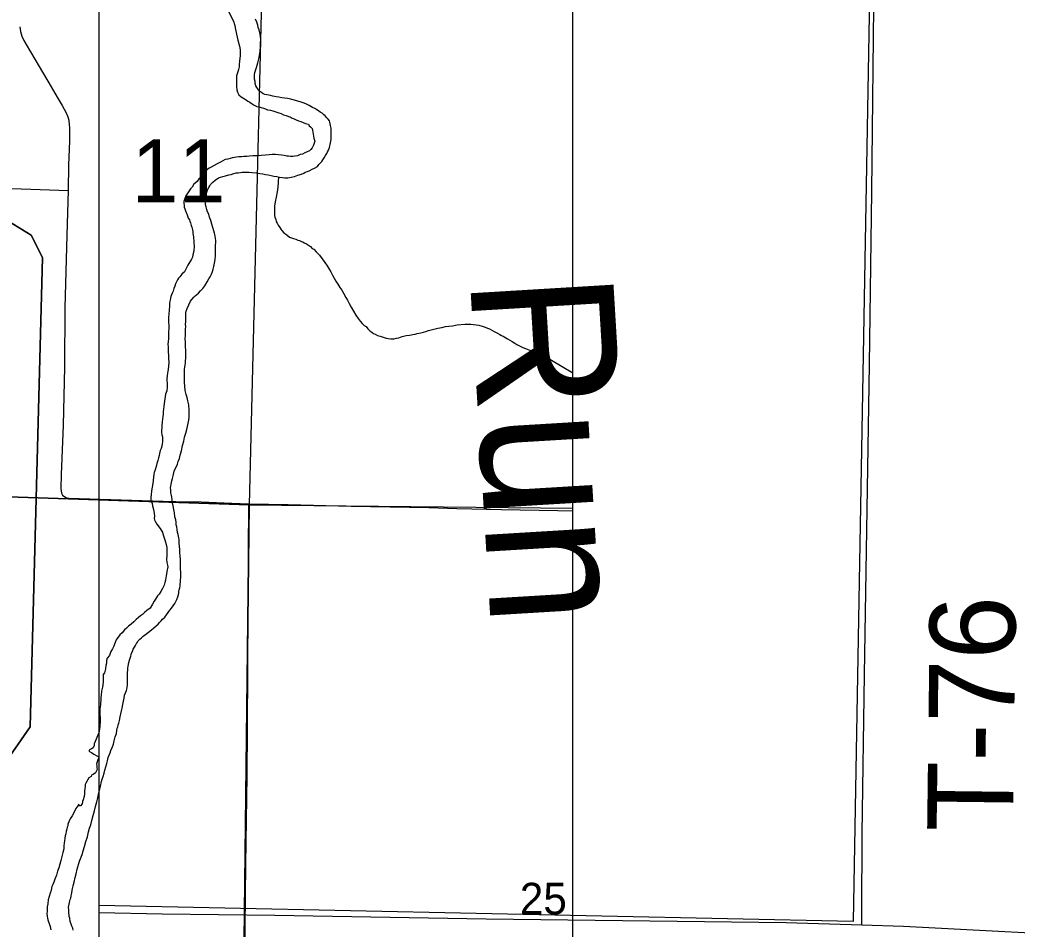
# Model space of a CAD drawing. Extents: x 0 to 68, y 0 to 52.9.
# Drawn here: x 49.378 to 51.122, y 39.684 to 41.274 of the extents above; entities that cross this region are included whole.
import ezdxf

# ---------------------------------------------------------------- set-up
doc = ezdxf.new("R2010")
doc.units = 0
for name, color, linetype in [('Default', 7, 'Continuous'), ('GM_X_County_Road', 7, 'Continuous'), ('GM_X_Minor_Lake', 7, 'Continuous'), ('GM_X_Minor_River', 7, 'Continuous'), ('GM_X_Minor_River_Text', 7, 'Continuous'), ('GM_X_Township_Road', 7, 'Continuous'), ('GM_X_Township_Road_Text', 7, 'Continuous')]:
    doc.layers.add(name, color=color, linetype=linetype)

msp = doc.modelspace()

# ---------------------------------------------------------------- linework, layer by layer
at = {"layer": 'Default'}
for p, q in [((49.5172, 34.4614), (49.5172, 52.9414)), ((50.3451, 32.7683), (50.3451, 42.0083))]:
    msp.add_line(p, q, dxfattribs=at)
for points in [[(49.5172, 42.3674), (50.8824, 42.3391), (50.8358, 39.6972), (49.5172, 39.725)], [(49.7428, 41.2905), (49.7526, 41.2698), (49.7531, 41.2673), (49.754, 41.2637), (49.755, 41.2597), (49.7574, 41.2486), (49.7597, 41.2381), (49.7621, 41.228), (49.7636, 41.2214), (49.7635, 41.2169), (49.7635, 41.2129), (49.7634, 41.2104), (49.7629, 41.2074), (49.7623, 41.2009), (49.7617, 41.1963), (49.7617, 41.1918), (49.7606, 41.1873), (49.7595, 41.1828), (49.7585, 41.1793), (49.7574, 41.1758), (49.7569, 41.1708), (49.7572, 41.1572), (49.7576, 41.1517), (49.7586, 41.1477), (49.7611, 41.1426), (49.7655, 41.1395), (49.771, 41.136), (49.774, 41.1339), (49.777, 41.1319), (49.7805, 41.1298), (49.7845, 41.1272), (49.788, 41.1247), (49.7925, 41.1226), (49.7965, 41.1216), (49.8001, 41.1205), (49.8041, 41.1194), (49.8081, 41.1184), (49.8116, 41.1168), (49.8166, 41.1158), (49.8206, 41.1147), (49.8241, 41.1137), (49.8277, 41.1126), (49.8312, 41.1111), (49.8352, 41.11), (49.8392, 41.1079), (49.8442, 41.1064), (49.8482, 41.1048), (49.8512, 41.1043), (49.8547, 41.1022), (49.8577, 41.1007), (49.8617, 41.0991), (49.8657, 41.0975), (49.8697, 41.096), (49.8738, 41.0944), (49.8778, 41.0929), (49.8803, 41.0923), (49.8828, 41.0913)], [(49.8893, 41.0129), (49.8934, 41.0148), (49.8985, 41.0173), (49.901, 41.0207), (49.9036, 41.0232), (49.9061, 41.0262), (49.9082, 41.0292), (49.9107, 41.0327), (49.9128, 41.0367), (49.9149, 41.0401), (49.9164, 41.0431), (49.918, 41.0461), (49.9195, 41.0506), (49.9216, 41.0586), (49.9222, 41.0616), (49.9227, 41.0646), (49.9228, 41.0687), (49.9228, 41.0727), (49.9229, 41.0762), (49.9229, 41.0792), (49.9224, 41.0817), (49.9225, 41.0842), (49.9215, 41.0893), (49.9211, 41.0918), (49.9201, 41.0948), (49.9196, 41.0973), (49.9176, 41.1004), (49.9151, 41.1024), (49.9122, 41.106), (49.9097, 41.108), (49.9067, 41.1106), (49.9037, 41.1126), (49.9007, 41.1147), (49.8977, 41.1167), (49.8942, 41.1188), (49.8902, 41.1208), (49.8842, 41.1239), (49.8797, 41.1265), (49.8752, 41.1281), (49.8702, 41.1301), (49.8642, 41.1317), (49.8581, 41.1333), (49.8521, 41.1349), (49.8466, 41.1365), (49.8416, 41.137), (49.8365, 41.1376), (49.831, 41.1387), (49.8265, 41.1392), (49.8204, 41.1403), (49.8164, 41.1414), (49.8134, 41.1419), (49.8099, 41.1425), (49.8064, 41.1435), (49.8039, 41.1446), (49.8009, 41.1466), (49.7974, 41.1492), (49.7949, 41.1517), (49.7924, 41.1558), (49.791, 41.1583), (49.79, 41.1623), (49.7895, 41.1658), (49.7886, 41.1704), (49.7886, 41.1744), (49.7887, 41.1779), (49.7892, 41.1819), (49.7903, 41.1854), (49.7919, 41.1904), (49.7934, 41.1944), (49.7945, 41.1989), (49.7956, 41.2034), (49.7966, 41.2079), (49.7972, 41.2125), (49.7977, 41.215), (49.7983, 41.2195), (49.7989, 41.226), (49.799, 41.2335), (49.7995, 41.2395), (49.7991, 41.2441), (49.7987, 41.2486), (49.7977, 41.2511), (49.7967, 41.2562), (49.7953, 41.2607), (49.7943, 41.2647), (49.7924, 41.2698), (49.7904, 41.2753)], [(49.8828, 41.0913), (49.8843, 41.0888), (49.8867, 41.0867), (49.8897, 41.0837), (49.8902, 41.0811), (49.8911, 41.0741), (49.8925, 41.0671), (49.894, 41.0615), (49.8919, 41.055), (49.8893, 41.05), (49.8873, 41.047), (49.8847, 41.0451), (49.8807, 41.0431), (49.8766, 41.0411), (49.8726, 41.0392), (49.8685, 41.0382), (49.864, 41.0363), (49.8594, 41.0353), (49.8554, 41.0349), (49.8518, 41.0349), (49.8483, 41.0355), (49.8453, 41.0355), (49.8403, 41.0366), (49.8358, 41.0372), (49.8307, 41.0377), (49.8252, 41.0383), (49.8197, 41.0384), (49.8141, 41.0379), (49.8081, 41.0375), (49.8005, 41.0366), (49.7924, 41.0362), (49.7859, 41.0358), (49.7798, 41.0354), (49.7753, 41.0349), (49.7698, 41.035), (49.7657, 41.0346), (49.7612, 41.0341), (49.7572, 41.0337), (49.7536, 41.0332), (49.7501, 41.0323), (49.7461, 41.0313), (49.742, 41.0304), (49.7375, 41.0294), (49.7334, 41.0275), (49.7294, 41.025), (49.7233, 41.0221), (49.7126, 41.0162), (49.7096, 41.0147), (49.704, 41.0103), (49.7009, 41.0073), (49.6984, 41.0043), (49.6953, 40.9998), (49.6912, 40.9959), (49.6886, 40.9914), (49.6851, 40.9884), (49.6825, 40.9864), (49.6795, 40.9815), (49.6769, 40.9785), (49.6743, 40.975), (49.6718, 40.9715), (49.6697, 40.968), (49.6682, 40.9655), (49.6671, 40.963), (49.6661, 40.96), (49.665, 40.9565), (49.665, 40.9525), (49.6655, 40.95), (49.6659, 40.9465), (49.6669, 40.9435), (49.6679, 40.9399), (49.6693, 40.9369), (49.6703, 40.9344), (49.6713, 40.9313), (49.6727, 40.9273), (49.6747, 40.9243), (49.6757, 40.9217), (49.6767, 40.9192), (49.6781, 40.9142), (49.6791, 40.9111), (49.68, 40.9066), (49.6805, 40.9036), (49.6809, 40.9001), (49.6819, 40.8945), (49.6828, 40.885), (49.6832, 40.8769), (49.6826, 40.8709), (49.682, 40.8669), (49.681, 40.8629), (49.6799, 40.8589), (49.6784, 40.8554), (49.6722, 40.8449), (49.6696, 40.8405), (49.666, 40.8335), (49.6614, 40.829), (49.6583, 40.8245), (49.6558, 40.8221), (49.6537, 40.8191), (49.6522, 40.8156), (49.6506, 40.8121), (49.6491, 40.8081), (49.6475, 40.8041)], [(49.6686, 40.6823), (49.6687, 40.6883), (49.6683, 40.6953), (49.6679, 40.7034), (49.668, 40.7104), (49.6675, 40.7164), (49.6681, 40.7214), (49.6677, 40.7275), (49.6678, 40.733), (49.6683, 40.7375), (49.6679, 40.742), (49.6684, 40.746), (49.6685, 40.7506), (49.6685, 40.7546), (49.6686, 40.7581), (49.6686, 40.7616), (49.6692, 40.7646), (49.6707, 40.7691), (49.6769, 40.7821), (49.679, 40.7846), (49.6826, 40.7891), (49.6851, 40.791), (49.6877, 40.7935), (49.6907, 40.796), (49.6943, 40.7999), (49.6984, 40.8044), (49.702, 40.8089), (49.7061, 40.8159), (49.7086, 40.8209), (49.7112, 40.8248), (49.7133, 40.8293), (49.7149, 40.8338), (49.7164, 40.8378), (49.7175, 40.8423), (49.7186, 40.8483), (49.7197, 40.8549), (49.7202, 40.8619), (49.7203, 40.8699), (49.7205, 40.8785), (49.721, 40.8855), (49.7211, 40.888), (49.7206, 40.8915), (49.7197, 40.896), (49.7187, 40.9006), (49.7173, 40.9051), (49.7158, 40.9107), (49.7139, 40.9167), (49.7125, 40.9228), (49.71, 40.9288), (49.7086, 40.9339), (49.7066, 40.9379), (49.7051, 40.9424), (49.7042, 40.947), (49.7032, 40.951), (49.7028, 40.955), (49.7029, 40.9606), (49.7034, 40.9651), (49.704, 40.9686), (49.705, 40.9726), (49.7066, 40.9766), (49.7087, 40.9806), (49.7107, 40.9836), (49.7117, 40.9861), (49.7158, 40.99), (49.7199, 40.9935), (49.7255, 40.9974), (49.729, 40.9989), (49.7331, 40.9998), (49.7381, 41.0013), (49.7437, 41.0027), (49.7477, 41.0037), (49.7523, 41.0051), (49.7563, 41.0061), (49.7603, 41.0065), (49.7644, 41.007), (49.7669, 41.0074), (49.7699, 41.0074), (49.774, 41.0078), (49.7785, 41.0078), (49.7845, 41.0072), (49.7921, 41.0066), (49.7981, 41.005), (49.8031, 41.0044), (49.8076, 41.0034), (49.8127, 41.0028), (49.8177, 41.0017), (49.8227, 41.0007), (49.8277, 41.0001), (49.8323, 40.999), (49.8373, 40.998), (49.8418, 40.9979), (49.8468, 40.9978), (49.8529, 40.9988), (49.8585, 41.0002), (49.8645, 41.0021), (49.8706, 41.0041), (49.8746, 41.0055), (49.8772, 41.0075), (49.8812, 41.0089), (49.8853, 41.0104), (49.8893, 41.0129)], [(49.6475, 40.8041), (49.6464, 40.7996), (49.6449, 40.7961), (49.6433, 40.7931), (49.6423, 40.7901), (49.6417, 40.7871), (49.6412, 40.7836), (49.6401, 40.7791), (49.6401, 40.773), (49.6395, 40.766), (49.6389, 40.7595), (49.6383, 40.7535), (49.6382, 40.7485), (49.6382, 40.7454), (49.6386, 40.7394), (49.6386, 40.7344), (49.6385, 40.7284), (49.6384, 40.7228), (49.6383, 40.7168), (49.6378, 40.7108), (49.6372, 40.7068), (49.6377, 40.7023), (49.6376, 40.6977), (49.6375, 40.6927), (49.638, 40.6877), (49.6384, 40.6822), (49.6388, 40.6746), (49.6382, 40.6681), (49.6377, 40.6631), (49.6371, 40.6591), (49.6366, 40.6566), (49.636, 40.651), (49.6354, 40.647), (49.6354, 40.6435), (49.6358, 40.6385), (49.6358, 40.632), (49.6352, 40.6249), (49.6331, 40.6194), (49.6304, 40.6029), (49.6298, 40.5979), (49.6292, 40.5934), (49.6287, 40.5889), (49.6286, 40.5843), (49.6281, 40.5803), (49.6275, 40.5758), (49.6269, 40.5708), (49.6263, 40.5643), (49.6263, 40.5603), (49.6262, 40.5562), (49.6262, 40.5527), (49.6266, 40.5482), (49.6276, 40.5447), (49.6276, 40.5412), (49.6275, 40.5361), (49.627, 40.5326), (49.6264, 40.5286), (49.6253, 40.5246), (49.6238, 40.5206), (49.6227, 40.5156), (49.6217, 40.5121), (49.6206, 40.5081), (49.6195, 40.5031), (49.618, 40.4981), (49.6164, 40.4926), (49.6148, 40.4871), (49.6132, 40.4826), (49.6127, 40.4791), (49.6121, 40.4746), (49.6115, 40.4685), (49.611, 40.463), (49.6094, 40.457), (49.6083, 40.4505), (49.6077, 40.4435), (49.6071, 40.439), (49.6076, 40.4359), (49.6081, 40.4324), (49.6095, 40.4284), (49.6105, 40.4239), (49.6119, 40.4178), (49.6133, 40.4113), (49.6138, 40.4062), (49.6132, 40.4022), (49.6137, 40.3997), (49.6157, 40.3962), (49.6181, 40.3921), (49.6236, 40.3845), (49.6256, 40.3815), (49.6275, 40.3779), (49.6285, 40.3754), (49.6295, 40.3719), (49.6309, 40.3683), (49.6319, 40.3648), (49.6328, 40.3608), (49.6343, 40.3562), (49.6352, 40.3512), (49.6352, 40.3462), (49.6351, 40.3417), (49.6351, 40.3371), (49.635, 40.3306), (49.6354, 40.3251), (49.6364, 40.3206)], [(49.594, 40.1961), (49.5981, 40.199), (49.6032, 40.203), (49.6083, 40.2074), (49.6128, 40.2109), (49.6169, 40.2143), (49.62, 40.2173), (49.6225, 40.2203), (49.6256, 40.2233), (49.6276, 40.2262), (49.6317, 40.2292), (49.6348, 40.2337), (49.6378, 40.2377), (49.6404, 40.2416), (49.6435, 40.2451), (49.6465, 40.2491), (49.6491, 40.2531), (49.6512, 40.2571), (49.6527, 40.2606), (49.6548, 40.2651), (49.6564, 40.2716), (49.6564, 40.2746), (49.657, 40.2771), (49.658, 40.2806), (49.6586, 40.2841), (49.6586, 40.2876), (49.6592, 40.2906), (49.6592, 40.2946), (49.6598, 40.2987), (49.6598, 40.3027), (49.6598, 40.3057), (49.6599, 40.3087), (49.6594, 40.3127), (49.659, 40.3172), (49.6591, 40.3233), (49.6592, 40.3303), (49.6587, 40.3368), (49.6583, 40.3424), (49.6579, 40.3479), (49.6574, 40.3529), (49.657, 40.3595), (49.6566, 40.3645), (49.6561, 40.368), (49.6556, 40.371), (49.6552, 40.3741), (49.6542, 40.3776), (49.6533, 40.3826), (49.6528, 40.3871), (49.6519, 40.3907), (49.6514, 40.3957), (49.651, 40.3997), (49.6495, 40.4048), (49.6486, 40.4118), (49.6477, 40.4178), (49.6462, 40.4239), (49.6453, 40.4294), (49.6444, 40.436), (49.6434, 40.442), (49.6425, 40.447), (49.6421, 40.4521), (49.6416, 40.4556), (49.6421, 40.4586), (49.6427, 40.4621), (49.6443, 40.4676), (49.6453, 40.4721), (49.6464, 40.4766), (49.6475, 40.4816), (49.648, 40.4846), (49.6537, 40.4971), (49.6553, 40.5016), (49.6573, 40.5066), (49.6589, 40.5126), (49.661, 40.5201), (49.6627, 40.5296), (49.6648, 40.5372), (49.6664, 40.5442), (49.6685, 40.5512), (49.6701, 40.5577), (49.6717, 40.5627), (49.6727, 40.5687), (49.6738, 40.5737), (49.6744, 40.5792), (49.6744, 40.5847), (49.6745, 40.5913), (49.6736, 40.6008), (49.6722, 40.6079), (49.6708, 40.6134), (49.6693, 40.619), (49.6674, 40.626), (49.6665, 40.6336), (49.6661, 40.6396), (49.6661, 40.6446), (49.6662, 40.6501), (49.6663, 40.6547), (49.6663, 40.6582), (49.6664, 40.6622), (49.6669, 40.6672), (49.6675, 40.6702), (49.668, 40.6737), (49.6681, 40.6777), (49.6686, 40.6823)], [(50.3451, 39.0938), (49.764, 39.105), (49.7795, 40.4261), (50.3451, 40.4201)], [(49.6364, 40.3206), (49.6368, 40.3175), (49.6363, 40.3145), (49.6358, 40.312), (49.6352, 40.309), (49.6347, 40.305), (49.6341, 40.301), (49.6336, 40.2985), (49.633, 40.294), (49.632, 40.29), (49.6304, 40.2855), (49.6278, 40.2795), (49.6247, 40.2745), (49.6216, 40.2695), (49.6191, 40.2665), (49.6175, 40.264), (49.6155, 40.2611), (49.6134, 40.2576), (49.6103, 40.2521), (49.6062, 40.2451), (49.6001, 40.2412), (49.596, 40.2377), (49.593, 40.2342), (49.5894, 40.2318), (49.5859, 40.2288), (49.5818, 40.2253), (49.5777, 40.2214), (49.5731, 40.2174), (49.5685, 40.2135), (49.565, 40.21), (49.5614, 40.207), (49.5573, 40.2021), (49.5532, 40.1986), (49.5466, 40.1896), (49.545, 40.1851), (49.544, 40.1821), (49.5424, 40.1787), (49.5403, 40.1742), (49.5373, 40.1692), (49.5352, 40.1622), (49.5311, 40.1577), (49.5295, 40.1537), (49.5295, 40.1487), (49.5289, 40.1447), (49.5278, 40.1392), (49.5262, 40.1322), (49.5242, 40.1292), (49.5241, 40.1241), (49.5241, 40.1206), (49.524, 40.1156), (49.5229, 40.1071), (49.5213, 40.1001), (49.5207, 40.093), (49.5201, 40.089), (49.5201, 40.0835), (49.5195, 40.0795), (49.5195, 40.076), (49.5189, 40.0725), (49.5184, 40.069), (49.5183, 40.0665), (49.5183, 40.064), (49.5183, 40.0609), (49.5182, 40.0574), (49.5187, 40.0549), (49.5186, 40.0494), (49.5186, 40.0444), (49.518, 40.0414), (49.518, 40.0383), (49.5174, 40.0333), (49.5163, 40.0273), (49.508, 40.0078), (49.508, 40.0048), (49.5064, 40.0008), (49.5034, 39.9994), (49.4998, 39.9974), (49.4988, 39.9949), (49.5038, 39.9928), (49.5078, 39.9898), (49.5138, 39.9862), (49.5163, 39.9856), (49.5158, 39.9831), (49.5147, 39.9801), (49.5132, 39.9766), (49.5121, 39.9726), (49.5126, 39.9701), (49.5131, 39.9666), (49.5135, 39.9631), (49.5104, 39.9571), (49.5064, 39.9546), (49.5038, 39.9531), (49.5028, 39.9506), (49.4987, 39.9482), (49.4936, 39.9392), (49.4925, 39.9367), (49.4925, 39.9337), (49.4919, 39.9292), (49.4914, 39.9252), (49.4913, 39.9212), (49.4908, 39.9161), (49.4892, 39.9101), (49.4881, 39.9071)], [(49.4664, 39.6975), (49.4654, 39.703), (49.4644, 39.706), (49.4645, 39.7086), (49.464, 39.7126), (49.4641, 39.7176), (49.4636, 39.7226), (49.4647, 39.7276), (49.4658, 39.7332), (49.4663, 39.7357), (49.4674, 39.7382), (49.4679, 39.7422), (49.4685, 39.7447), (49.469, 39.7472), (49.4696, 39.7517), (49.4701, 39.7547), (49.4717, 39.7597), (49.4733, 39.7662), (49.4749, 39.7742), (49.477, 39.7807), (49.4786, 39.7887), (49.4828, 39.8027), (49.4849, 39.8087), (49.487, 39.8142), (49.4891, 39.8207), (49.4912, 39.8282), (49.4938, 39.8373), (49.4964, 39.8453), (49.4985, 39.8543), (49.5001, 39.8603), (49.5022, 39.8663), (49.5043, 39.8738), (49.5065, 39.8828), (49.5086, 39.8908), (49.5107, 39.8983), (49.5128, 39.9063), (49.5144, 39.9133), (49.516, 39.9193), (49.5192, 39.9339), (49.5197, 39.9369), (49.5203, 39.9394), (49.5213, 39.9419), (49.5224, 39.9459), (49.5239, 39.9509), (49.5255, 39.9564), (49.5271, 39.9619), (49.5287, 39.9679), (49.5303, 39.9734), (49.5313, 39.9784), (49.5329, 39.9839), (49.5345, 39.9879), (49.536, 39.9924), (49.5376, 39.9964), (49.5397, 40.0014), (49.5418, 40.0074), (49.5434, 40.0134), (49.5449, 40.0199), (49.547, 40.0259), (49.5481, 40.0314), (49.5487, 40.0354), (49.5497, 40.0379), (49.5503, 40.0409), (49.5513, 40.0439), (49.5524, 40.0489), (49.5534, 40.055), (49.555, 40.0605), (49.5561, 40.0655), (49.5572, 40.0705), (49.5583, 40.0765), (49.5593, 40.0825), (49.5609, 40.088), (49.5615, 40.093), (49.563, 40.097), (49.5646, 40.101), (49.5657, 40.106), (49.5668, 40.1115), (49.5668, 40.1155), (49.5663, 40.1181), (49.5664, 40.1221), (49.5664, 40.1271), (49.5665, 40.1321), (49.5671, 40.1376), (49.5671, 40.1407), (49.5677, 40.1432), (49.5682, 40.1472), (49.5688, 40.1502), (49.5698, 40.1542), (49.5714, 40.1577), (49.5724, 40.1612), (49.5729, 40.1637), (49.5735, 40.1662), (49.5761, 40.1707), (49.5766, 40.1732), (49.5787, 40.1767), (49.5807, 40.1797), (49.5823, 40.1831), (49.5838, 40.1856), (49.5853, 40.1881), (49.5879, 40.1911), (49.5909, 40.1931), (49.594, 40.1961)], [(49.4881, 39.9071), (49.4871, 39.9031), (49.4845, 39.8997), (49.4815, 39.8997), (49.4815, 39.9027), (49.4795, 39.8997), (49.4764, 39.8947), (49.4733, 39.8883), (49.4697, 39.8823), (49.4661, 39.8768), (49.4651, 39.8743), (49.464, 39.8718), (49.4624, 39.8673), (49.4619, 39.8648), (49.4609, 39.8623), (49.4603, 39.8588), (49.4593, 39.8553), (49.4587, 39.8508), (49.4577, 39.8473), (49.4571, 39.8428), (49.4565, 39.8382), (49.456, 39.8342), (49.4554, 39.8297), (49.4549, 39.8242), (49.4533, 39.8182), (49.4517, 39.8112), (49.4501, 39.8042), (49.448, 39.7977), (49.4464, 39.7912), (49.4443, 39.7852), (49.4422, 39.7782), (49.4396, 39.7712), (49.4375, 39.7662), (49.4359, 39.7622), (49.4344, 39.7582), (49.4338, 39.7557), (49.4328, 39.7517), (49.4312, 39.7467), (49.4296, 39.7412), (49.428, 39.7352), (49.427, 39.7281), (49.4259, 39.7231), (49.4258, 39.7186), (49.4258, 39.7151), (49.4257, 39.7106), (49.4262, 39.7066), (49.4266, 39.703), (49.4271, 39.7), (49.4286, 39.6965), (49.4295, 39.6935), (49.431, 39.6884), (49.4324, 39.6829)], [(49.4717, 39.6823), (49.4707, 39.6854), (49.4693, 39.6889), (49.4678, 39.6929), (49.4664, 39.6975)]]:
    msp.add_lwpolyline(points, dxfattribs=at)
for points in [[(48.4986, 41.784), (49.8114, 41.7401), (49.7795, 40.4261), (48.4787, 40.4689)], [(48.4787, 40.4689), (49.7795, 40.4261), (49.764, 39.105), (48.4576, 39.1473)]]:
    msp.add_lwpolyline(points, close=True, dxfattribs=at)
at = {"layer": 'GM_X_County_Road'}
for points in [[(49.5172, 39.7129), (49.6273, 39.7104), (49.8243, 39.7084), (50.1935, 39.7021), (50.7186, 39.6955), (50.8504, 39.6914)], [(50.8504, 39.6914), (50.9236, 39.6891), (51.3006, 39.6695), (52.0217, 39.6321), (52.1863, 39.6234)]]:
    msp.add_lwpolyline(points, dxfattribs=at)
at = {"layer": 'GM_X_Minor_Lake'}
for points in [[(48.6777, 39.9766), (48.7212, 39.9941), (49.2861, 39.9801), (49.3448, 39.9638), (49.3961, 40.0374), (49.4181, 40.8583), (49.3979, 40.8973), (49.3599, 40.9204), (49.2507, 40.9258), (49.1199, 40.9341), (48.9581, 41.0472), (48.1175, 41.0708), (48.0845, 41.0532)], [(49.3599, 40.9204), (49.3979, 40.8973), (49.4181, 40.8583), (49.3961, 40.0374), (49.3448, 39.9638)]]:
    msp.add_lwpolyline(points, dxfattribs=at)
at = {"layer": 'GM_X_Minor_River'}
for points in [[(49.8307, 40.9994), (49.8295, 40.9815), (49.8284, 40.973), (49.8263, 40.964), (49.8247, 40.9554), (49.8236, 40.9479), (49.8235, 40.9409), (49.8234, 40.9354), (49.8234, 40.9319), (49.8243, 40.9288), (49.8258, 40.9248), (49.8267, 40.9213), (49.8282, 40.9182), (49.8302, 40.9147), (49.8327, 40.9106), (49.8346, 40.9081), (49.8366, 40.9056), (49.8401, 40.9015), (49.8451, 40.8979), (49.8501, 40.8938), (49.8566, 40.8917), (49.8606, 40.8902), (49.8646, 40.8886), (49.8671, 40.8881), (49.8706, 40.8865), (49.8731, 40.8855), (49.8756, 40.884), (49.8796, 40.8824), (49.8831, 40.8798), (49.8866, 40.8773), (49.8896, 40.8742), (49.8921, 40.8727), (49.8966, 40.8681), (49.8996, 40.8651), (49.902, 40.8625), (49.9114, 40.8493), (49.9154, 40.8438), (49.9189, 40.8382), (49.9218, 40.8331), (49.9248, 40.8276), (49.9277, 40.822), (49.9307, 40.8169), (49.9341, 40.8114), (49.9376, 40.8058), (49.9411, 40.8012), (49.944, 40.7962), (49.9484, 40.7886), (49.9514, 40.7835), (49.9544, 40.7779), (49.9578, 40.7714), (49.9617, 40.7643), (49.9657, 40.7572), (49.9696, 40.7516), (49.9736, 40.7471), (49.9771, 40.743), (49.9806, 40.7394), (49.9836, 40.7374), (49.987, 40.7338), (49.9905, 40.7298), (49.9935, 40.7277), (49.9965, 40.7257), (49.9995, 40.7241), (50.0035, 40.7221), (50.0085, 40.7205), (50.0135, 40.7189), (50.0186, 40.7173), (50.0226, 40.7168), (50.0271, 40.7162), (50.0326, 40.7161), (50.0372, 40.7171), (50.0412, 40.718), (50.0468, 40.72), (50.0539, 40.7219), (50.0599, 40.7228), (50.0655, 40.7237), (50.0695, 40.7242), (50.073, 40.7252), (50.0796, 40.7266), (50.0841, 40.7275), (50.0882, 40.729), (50.0927, 40.7304), (50.1094, 40.7347), (50.116, 40.7361), (50.1225, 40.7376), (50.1286, 40.738), (50.1351, 40.7389), (50.1432, 40.7403), (50.1563, 40.7416), (50.1619, 40.7416), (50.1669, 40.7415), (50.176, 40.7404), (50.181, 40.7398), (50.1885, 40.7377), (50.192, 40.7367), (50.196, 40.7346), (50.1995, 40.7335), (50.2035, 40.7315), (50.208, 40.7289), (50.2135, 40.7258), (50.2175, 40.7238), (50.2205, 40.7222)], [(50.2205, 40.7222), (50.2235, 40.7207), (50.228, 40.7181), (50.231, 40.716), (50.235, 40.714), (50.239, 40.7114), (50.244, 40.7083), (50.2475, 40.7063), (50.251, 40.7042), (50.2545, 40.7027), (50.258, 40.7011), (50.2626, 40.6991), (50.2681, 40.697), (50.2736, 40.6949), (50.2781, 40.6928), (50.2826, 40.6908), (50.2906, 40.6881), (50.2976, 40.685), (50.3011, 40.684), (50.3046, 40.6814), (50.3081, 40.6789), (50.3451, 40.6567)]]:
    msp.add_lwpolyline(points, dxfattribs=at)
at = {"layer": 'GM_X_Township_Road'}
for points in [[(50.8504, 39.6914), (50.8505, 39.7111), (50.8515, 39.8505), (50.8556, 40.1293), (50.8639, 40.6705), (50.8682, 40.9739), (50.872, 41.3511), (50.8815, 41.9005), (50.8854, 42.2449), (50.887, 42.337)], [(49.3783, 41.2614), (49.3796, 41.2533), (49.382, 41.2455), (49.3853, 41.238), (49.3892, 41.2308), (49.4123, 41.192), (49.4329, 41.1565), (49.4433, 41.1388), (49.4521, 41.1243), (49.4593, 41.1113), (49.4622, 41.1041), (49.4637, 41.0983), (49.4647, 41.0896), (49.4648, 41.0862), (49.4651, 41.078), (49.4649, 41.0615), (49.4636, 41.0205), (49.4626, 40.9754)], [(49.3145, 40.9808), (49.4626, 40.9754)], [(49.4626, 40.9754), (49.4606, 40.8976), (49.4571, 40.7704), (49.4562, 40.6665), (49.4542, 40.565), (49.4519, 40.5076), (49.4508, 40.4788), (49.4501, 40.4542), (49.4503, 40.4501), (49.4511, 40.4462), (49.4531, 40.4425), (49.4586, 40.4386), (49.4642, 40.4377), (49.6477, 40.4318)], [(49.6477, 40.4318), (49.6512, 40.4317), (49.6951, 40.4309), (49.7488, 40.4289), (49.7788, 40.4277)], [(49.7653, 39.1063), (49.7656, 39.1195), (49.7664, 39.2263), (49.769, 39.4356), (49.7707, 39.5628), (49.7715, 39.6326), (49.7734, 39.7968), (49.7755, 39.9528), (49.7763, 40.0348), (49.7778, 40.2442), (49.7779, 40.3427), (49.7788, 40.4277)], [(49.7788, 40.4277), (49.8472, 40.4263), (49.9579, 40.4235), (50.0932, 40.421), (50.1424, 40.4195), (50.2203, 40.4179), (50.3188, 40.4158), (50.3451, 40.4153)]]:
    msp.add_lwpolyline(points, dxfattribs=at)

# ---------------------------------------------------------------- texts
at = {"layer": 'Default'}
for s, height, p in [('11', 0.1105, (49.5734, 40.9546)), ('25', 0.05525, (50.2526, 39.7097))]:
    msp.add_text(s, height=height, rotation=0, dxfattribs=at).set_placement(p)
at = {"layer": 'GM_X_Minor_River_Text'}
msp.add_text('Run', height=0.2501, rotation=273.4451, dxfattribs=at).set_placement((50.1651, 40.8232))
at = {"layer": 'GM_X_Township_Road_Text'}
msp.add_text('T-76', height=0.15, rotation=89.2917, dxfattribs=at).set_placement((51.1148, 39.8534))

doc.saveas('drawing.dxf')
